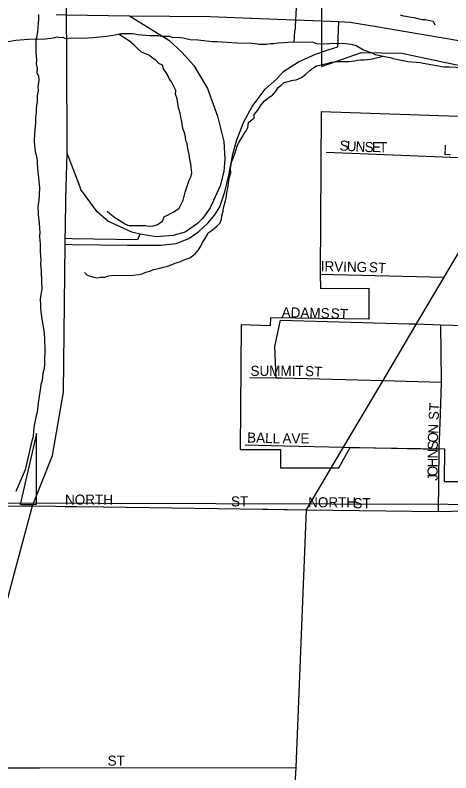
# Model space of a CAD drawing. Extents: x 1588073 to 2013523, y 1090242 to 1357120.
# Drawn here: x 1798757 to 1800917, y 1223743 to 1227498 of the extents above; entities that cross this region are included whole.
import ezdxf

# ---------------------------------------------------------------- set-up
doc = ezdxf.new("R2010")
doc.units = 0
for name, color, linetype in [('GM_X_City_Street', 7, 'Continuous'), ('GM_X_City_Street_Text', 7, 'Continuous'), ('GM_X_Corporation', 7, 'Continuous'), ('GM_X_County_Road', 7, 'Continuous'), ('GM_X_Interchange_Ramps', 7, 'Continuous'), ('GM_X_Minor_River', 7, 'Continuous'), ('GM_X_Section', 7, 'Continuous'), ('GM_X_State_Route', 7, 'Continuous'), ('GM_X_Township_Subdivision', 7, 'Continuous'), ('GM_X_Township_Subdivision_Text', 7, 'Continuous'), ('GM_X_US_Route', 7, 'Continuous')]:
    doc.layers.add(name, color=color, linetype=linetype)

msp = doc.modelspace()

# ---------------------------------------------------------------- linework, layer by layer
at = {"layer": 'GM_X_City_Street'}
for points in [[(1799006.2, 1226443.7), (1799007.7, 1226588.3), (1799015.6, 1226813.5)], [(1798843.2, 1225065.9), (1798942.8, 1225316.1), (1798997.5, 1225629.9), (1799005.3, 1226362.6), (1799005.6, 1226390.9), (1799006.2, 1226443.7)], [(1800201.9, 1225046.2), (1800332.9, 1225267.6)], [(1800856.5, 1225037.6), (1800858, 1225185.7)], [(1798501.3, 1223783.6), (1798574.1, 1224057.3), (1798658.5, 1224376.6), (1798754.2, 1224733.7), (1798843.2, 1225065.9)], [(1798632.2, 1225064.4), (1798790.4, 1225065.5)], [(1798843.2, 1225065.9), (1798958, 1225064.2), (1799005.8, 1225063.5), (1799060.6, 1225062.7)], [(1799060.6, 1225062.7), (1799197.2, 1225060.8), (1799984.5, 1225049.3)], [(1800031.1, 1221643.1), (1800031.1, 1221643.1), (1800047.7, 1221932.4), (1800071.5, 1222356), (1800150.7, 1223768.8), (1800201.9, 1225046.2)], [(1800093.2, 1225047.8), (1800106.2, 1225047.6), (1800201.9, 1225046.2)], [(1800201.9, 1225046.2), (1800856.5, 1225037.6), (1801303.3, 1225049.4), (1801324.7, 1225050)], [(1798506.3, 1223767.5), (1798506.3, 1223767.5), (1798877.6, 1223767.8), (1798877.6, 1223767.8)], [(1798877.6, 1223767.8), (1800150.7, 1223768.8)]]:
    msp.add_lwpolyline(points, dxfattribs=at)
at = {"layer": 'GM_X_Corporation'}
for points in [[(1800275.8, 1227597), (1800275.9, 1227243.8), (1800474.5, 1227312.3), (1800674.6, 1227308.8), (1801234.5, 1227190)], [(1801345.2, 1226981.8), (1800274.3, 1227018.9), (1800268.8, 1226214.5), (1800270.3, 1226144), (1800510.6, 1226144.1), (1800510.7, 1225991), (1800022.7, 1225998.4), (1800021.4, 1225958.4), (1799877.4, 1225963.4), (1799873.4, 1225344.6), (1800072.5, 1225344.7), (1800072.5, 1225254.6), (1800362.7, 1225254.7), (1800418.5, 1225356), (1800886.3, 1225348.3), (1800883.8, 1225186.9), (1801264, 1225187)]]:
    msp.add_lwpolyline(points, dxfattribs=at)
msp.add_lwpolyline([(1798781.4, 1225073.6), (1798862.5, 1225073.9), (1798862.4, 1225424.1)], close=True, dxfattribs=at)
at = {"layer": 'GM_X_County_Road'}
for points in [[(1800385.3, 1225356.1), (1800581.2, 1225687), (1800747.3, 1225967.3), (1800884.5, 1226198.9), (1800968.8, 1226341.2), (1801162.1, 1226667.6), (1801493, 1227179.7), (1801494.5, 1227182.6)], [(1800332.9, 1225267.6), (1800332.9, 1225267.6), (1800385.3, 1225356.1)], [(1798790.4, 1225065.5), (1798843.2, 1225065.9)], [(1799984.5, 1225049.3), (1800010.5, 1225049), (1800093.2, 1225047.8)]]:
    msp.add_lwpolyline(points, dxfattribs=at)
at = {"layer": 'GM_X_Interchange_Ramps'}
for points in [[(1799005.3, 1226362.6), (1799040.2, 1226361.8), (1799314, 1226357.2), (1799479.6, 1226357.2), (1799555.5, 1226366.4), (1799617.6, 1226391.7), (1799668.3, 1226426.3), (1799712, 1226467.7), (1799746.5, 1226509.1), (1799771.8, 1226548.2), (1799797.1, 1226621.9), (1799817.8, 1226711.6), (1799836.2, 1226808.2), (1799856.9, 1226879.6), (1799891.4, 1226969.3), (1799932.8, 1227045.2), (1799997.2, 1227130.4), (1800052.4, 1227181), (1800089.2, 1227220.2), (1800162.8, 1227266.2), (1800245.6, 1227305.3), (1800314.7, 1227328.3), (1800356.8, 1227341), (1800361.9, 1227466)], [(1799375.1, 1226412.6), (1799364.6, 1226385.2), (1799040.4, 1226390.1), (1799005.6, 1226390.9)]]:
    msp.add_lwpolyline(points, dxfattribs=at)
at = {"layer": 'GM_X_Minor_River'}
for points in [[(1800150.3, 1227539.1), (1800151.2, 1227529.3), (1800148.7, 1227507.3), (1800147.9, 1227467.3), (1800145.5, 1227447.3), (1800145.2, 1227431.3), (1800142.9, 1227417.3), (1800138.9, 1227363.9)], [(1798873.3, 1227500.6), (1798872.9, 1227478.6), (1798870, 1227438.6), (1798867.5, 1227414.6), (1798863, 1227388.7), (1798860.6, 1227370.7), (1798860.2, 1227348.7), (1798859.4, 1227314.6), (1798861, 1227292.6), (1798862.6, 1227274.5), (1798862.2, 1227256.5), (1798865.8, 1227234.4), (1798865.4, 1227214.4), (1798873, 1227196.2), (1798874.6, 1227176.1), (1798869.8, 1227140.2), (1798871.5, 1227124.1), (1798867, 1227100.2), (1798866.4, 1227070.1), (1798863.9, 1227048.2), (1798861.6, 1227034.2), (1798861.2, 1227016.2), (1798858.7, 1226988.2), (1798858.2, 1226964.1), (1798855.5, 1226930.1), (1798853, 1226910.2), (1798852.3, 1226874.1), (1798853.8, 1226852.1), (1798855.5, 1226838), (1798857.2, 1226821.9), (1798860.8, 1226803.8), (1798866.3, 1226779.7), (1798866, 1226763.7), (1798867.6, 1226743.6), (1798869.1, 1226719.6), (1798872.5, 1226693.4), (1798874.2, 1226675.4), (1798877.4, 1226641.3), (1798876.7, 1226607.2), (1798874.2, 1226579.2), (1798871.8, 1226561.3), (1798869.5, 1226545.3), (1798871, 1226525.2), (1798870.7, 1226509.2), (1798872.4, 1226493.2), (1798875.9, 1226469.1), (1798877.2, 1226439), (1798878.9, 1226422.9), (1798878.4, 1226400.9), (1798880, 1226380.8), (1798881.7, 1226364.8), (1798881, 1226330.7), (1798882.4, 1226302.7), (1798884.1, 1226286.6), (1798883.6, 1226264.6), (1798886.9, 1226228.5), (1798886.5, 1226210.4), (1798888.2, 1226196.4), (1798887.9, 1226180.4), (1798889, 1226140.3), (1798884.5, 1226114.3), (1798881.9, 1226088.4), (1798883.4, 1226062.3), (1798883, 1226042.3), (1798886.4, 1226016.2), (1798891.7, 1225982), (1798898.8, 1225935.8), (1798902, 1225897.7), (1798903.5, 1225873.6), (1798905.1, 1225857.6), (1798903.3, 1225767.4), (1798900.9, 1225747.5), (1798894.3, 1225721.6), (1798891.6, 1225687.6), (1798885.2, 1225667.7), (1798880.6, 1225639.7), (1798878.3, 1225621.7), (1798875.9, 1225605.8), (1798871.3, 1225575.8), (1798866.4, 1225529.8), (1798862, 1225513.9), (1798851, 1225464), (1798848.5, 1225438.1), (1798845.8, 1225408.1), (1798839.4, 1225388.1), (1798806.5, 1225244.6), (1798760.3, 1225137.3)], [(1800666.3, 1227499), (1800680.2, 1227494.7), (1800694.2, 1227492.5), (1800720, 1227487.9), (1800736, 1227485.6), (1800753.9, 1227481.3), (1800775.8, 1227476.8), (1800791.8, 1227476.5), (1800811.7, 1227472.1), (1800829.6, 1227467.7), (1800837.2, 1227449.6)], [(1798722.6, 1227367.4), (1798760.7, 1227374.7), (1798822.8, 1227379.5), (1798906.8, 1227379.8), (1798946.9, 1227385), (1798965, 1227390.7), (1798978.9, 1227386.4), (1798992.9, 1227388.1), (1799006.8, 1227381.8), (1799038.8, 1227385.2), (1799088.8, 1227384.2), (1799144.8, 1227387.1), (1799210.9, 1227393.8), (1799253, 1227401), (1799281.1, 1227406.4), (1799339.1, 1227407.3), (1799367, 1227402.7), (1799422.9, 1227397.6), (1799446.8, 1227397.1), (1799466.8, 1227396.7), (1799484.8, 1227394.3), (1799520.7, 1227393.6), (1799538.6, 1227387.3), (1799558.6, 1227388.9), (1799574.6, 1227386.6), (1799590.5, 1227386.2), (1799624.3, 1227377.6), (1799662.3, 1227374.8), (1799736.1, 1227367.3), (1799758, 1227366.9), (1799855.9, 1227360.9), (1799929.8, 1227359.5), (1799947.7, 1227357.1), (1799963.7, 1227354.8), (1800003.6, 1227354), (1800021.7, 1227357.6), (1800035.7, 1227357.3), (1800061.8, 1227360.8), (1800089.8, 1227362.3), (1800133.8, 1227365.4)], [(1799212.9, 1226526.4), (1799226.6, 1226514.1), (1799252.2, 1226495.6), (1799268, 1226485.3), (1799285.7, 1226472.9), (1799307.5, 1226460.5), (1799321.3, 1226456.2), (1799401.3, 1226454.6), (1799417.2, 1226452.3), (1799441.2, 1226453.8), (1799459.3, 1226459.4), (1799487.7, 1226476.9), (1799496.1, 1226498.8), (1799544.6, 1226523.8), (1799571, 1226541.3), (1799589.8, 1226581), (1799600.6, 1226620.9), (1799619.9, 1226680.6), (1799630.3, 1226700.4), (1799632.6, 1226716.4), (1799629.1, 1226742.5), (1799627.5, 1226760.6), (1799624, 1226782.7), (1799620.5, 1226806.8), (1799614.9, 1226828.9), (1799611.3, 1226845), (1799609.6, 1226861.1), (1799603.9, 1226875.2), (1799602.3, 1226895.3), (1799594.8, 1226919.4), (1799589.2, 1226935.6), (1799583.9, 1226969.7), (1799578.3, 1226991.9), (1799574.8, 1227012), (1799567.3, 1227038.2), (1799560.2, 1227082.4), (1799552.7, 1227106.6), (1799553.1, 1227124.6), (1799543.5, 1227144.8), (1799532, 1227167.1), (1799522.3, 1227181.3), (1799512.7, 1227201.5), (1799505, 1227215.7), (1799493.4, 1227231.9), (1799487.8, 1227250.1), (1799469.9, 1227258.4), (1799456.3, 1227272.7), (1799436.6, 1227287.1), (1799422.8, 1227297.4), (1799408.9, 1227303.7), (1799383.2, 1227314.2), (1799367.5, 1227328.6), (1799345.9, 1227351), (1799324.3, 1227369.5), (1799272.5, 1227402.2)], [(1800133.8, 1227365.4), (1800233.7, 1227363.4), (1800251.6, 1227357.1), (1800283.5, 1227356.4), (1800315.6, 1227357.8), (1800383.5, 1227358.4), (1800407.5, 1227356), (1800423.4, 1227353.6), (1800447.3, 1227347.1), (1800484.8, 1227326.4), (1800528.4, 1227309.5), (1800542.3, 1227303.2), (1800598, 1227292.1), (1800615.9, 1227287.7), (1800631.8, 1227283.4), (1800671.6, 1227274.6), (1800703.5, 1227267.9), (1800745.4, 1227265.1), (1800765.3, 1227262.7), (1800779.3, 1227260.4), (1800799.2, 1227256), (1800882.8, 1227242.3), (1800908.8, 1227241.8), (1801040.6, 1227235.2)], [(1799100.6, 1226222.2), (1799114.3, 1226209.9), (1799130.2, 1226203.6), (1799148.1, 1226199.2), (1799166, 1226196.9), (1799180.1, 1226198.6), (1799202.1, 1226200.2), (1799222.2, 1226205.8), (1799244.3, 1226209.3), (1799266.2, 1226206.9), (1799288.2, 1226208.5), (1799308.2, 1226208.1), (1799342.2, 1226209.4), (1799370.3, 1226212.8), (1799386.3, 1226216.5), (1799404.5, 1226224.2), (1799424.6, 1226229.8), (1799442.7, 1226237.4), (1799474.9, 1226244.8), (1799492.9, 1226248.5), (1799507, 1226252.2), (1799523.1, 1226257.9), (1799551.3, 1226269.3), (1799573.4, 1226274.9), (1799587.6, 1226282.6), (1799603.7, 1226288.3), (1799623.9, 1226295.9), (1799650.3, 1226315.4), (1799666.6, 1226335.1), (1799677, 1226353), (1799685.4, 1226370.8), (1799695.7, 1226386.6), (1799708.1, 1226404.4), (1799714.4, 1226418.3), (1799734.6, 1226431.9), (1799759.1, 1226453.5), (1799773.4, 1226469.2), (1799779.8, 1226487.1), (1799782, 1226501.1), (1799788.6, 1226527), (1799790.9, 1226543), (1799799.6, 1226576.9), (1799803.9, 1226590.8), (1799808.6, 1226626.8), (1799810.9, 1226640.7), (1799817.9, 1226688.7), (1799826.5, 1226718.5), (1799825, 1226738.6), (1799829.6, 1226768.6), (1799840.1, 1226794.4), (1799848.6, 1226816.2), (1799857.2, 1226848.1), (1799865.6, 1226866), (1799882.1, 1226893.7), (1799892.5, 1226911.5), (1799902.8, 1226925.3), (1799911.1, 1226941.2), (1799913.6, 1226965.2), (1799942.1, 1226988.6), (1799942.4, 1227004.7), (1799960.9, 1227026.3), (1799977.4, 1227054), (1799993.8, 1227073.8), (1800016.2, 1227091.3), (1800032.4, 1227101), (1800050.8, 1227122.7), (1800061.1, 1227138.5), (1800075.4, 1227150.2), (1800091.6, 1227163.9), (1800135.9, 1227175.1), (1800149.9, 1227176.8), (1800176.1, 1227188.3), (1800198.5, 1227205.9), (1800216.8, 1227221.5), (1800233, 1227235.2), (1800251.3, 1227246.9), (1800267.4, 1227250.6), (1800287.4, 1227254.2), (1800309.5, 1227259.8), (1800323.6, 1227265.5), (1800341.7, 1227267.1), (1800361.7, 1227268.7), (1800411.6, 1227267.7), (1800439.7, 1227271.2), (1800453.8, 1227274.9), (1800469.8, 1227276.6), (1800487.8, 1227276.2), (1800501.8, 1227278), (1800519.8, 1227279.6), (1800582.8, 1227294.9)]]:
    msp.add_lwpolyline(points, dxfattribs=at)
at = {"layer": 'GM_X_Section'}
msp.add_lwpolyline([(1796314.5, 1228634.1), (1797921.1, 1228670.8), (1801580.1, 1228628), (1801478.2, 1225070.5), (1796297.6, 1225086.2)], close=True, dxfattribs=at)
at = {"layer": 'GM_X_State_Route'}
for points in [[(1799013.3, 1227304.4), (1799012.4, 1227499.7), (1799023.8, 1228588.9), (1799024.2, 1228626.5), (1799028.6, 1229064.5)], [(1799324.1, 1227495.2), (1799518.9, 1227373.6), (1799584.1, 1227314.4), (1799643, 1227247.8), (1799711.6, 1227134.4), (1799760.7, 1226997.4), (1799792.5, 1226871.6), (1799796, 1226785), (1799792.5, 1226723.2), (1799773.1, 1226652.5), (1799723.6, 1226543), (1799688.3, 1226491.7), (1799661.8, 1226465.2), (1799600, 1226422.8), (1799538.2, 1226405.2), (1799458.7, 1226399.8), (1799375.1, 1226412.6), (1799335.7, 1226422.2), (1799216.7, 1226477.6), (1799164.4, 1226522.9), (1799083.6, 1226634.2), (1799079.2, 1226645.8)], [(1799079.2, 1226645.8), (1799053.2, 1226715.5), (1799015.6, 1226813.5), (1799013.3, 1227304.4)]]:
    msp.add_lwpolyline(points, dxfattribs=at)
at = {"layer": 'GM_X_Township_Subdivision'}
for points in [[(1801162.1, 1226667.6), (1800957.6, 1226791.2), (1800506.8, 1226808.4), (1800298.5, 1226817.8)], [(1800268.8, 1226214.5), (1800884.5, 1226198.9)], [(1800052.1, 1225700.8), (1800044.4, 1225855.1), (1800072.7, 1225987)], [(1800072.7, 1225987), (1800710.8, 1225968.4), (1800710.8, 1225968.4)], [(1800710.8, 1225968.4), (1800747.3, 1225967.3), (1800868.3, 1225963.8), (1801357.1, 1225949.5), (1801447.2, 1225946.9)], [(1800871.5, 1225685.8), (1800868.3, 1225963.8)], [(1799920.8, 1225702.5), (1800052.1, 1225700.8), (1800078.5, 1225700.1), (1800079.3, 1225700.1)], [(1800079.3, 1225700.1), (1800581.2, 1225687), (1800871.6, 1225679.3)], [(1800865.8, 1225519.2), (1800871.6, 1225679.3), (1800871.5, 1225685.8)], [(1800859.8, 1225352.5), (1800865.8, 1225519.2)], [(1799898.4, 1225368), (1800093.2, 1225363.2), (1800093.2, 1225363.2)], [(1800093.2, 1225363.2), (1800385.3, 1225356.1)], [(1800385.3, 1225356.1), (1800859.6, 1225346.8)], [(1800858, 1225185.7), (1800859.6, 1225346.8), (1800859.8, 1225352.5)]]:
    msp.add_lwpolyline(points, dxfattribs=at)
at = {"layer": 'GM_X_US_Route'}
for points in [[(1798960.8, 1227500.5), (1799012.4, 1227499.7), (1799324.1, 1227495.2)], [(1799324.1, 1227495.2), (1799724.5, 1227491.5), (1799925, 1227483.5)], [(1799925, 1227483.5), (1799928.4, 1227483.3), (1800143.4, 1227474.7)], [(1800143.4, 1227474.7), (1800148.9, 1227474.5), (1800361.9, 1227466), (1800418.9, 1227463.7), (1800567.8, 1227438.8)], [(1800567.8, 1227438.8), (1800587.2, 1227435.6), (1801542, 1227273.1), (1802152.3, 1227149.8)]]:
    msp.add_lwpolyline(points, dxfattribs=at)

# ---------------------------------------------------------------- texts
at = {"layer": 'GM_X_City_Street_Text'}
for s, p in [('NORTH', (1799004.4, 1225072)), ('ST', (1799827.2, 1225063.2)), ('NORTH', (1800210, 1225058.8)), ('ST', (1800434.4, 1225054.4)), ('ST', (1799215.6, 1223778.4))]:
    msp.add_text(s, height=50, rotation=0, dxfattribs=at).set_placement(p)
at = {"layer": 'GM_X_Township_Subdivision_Text'}
for s, rotation, p in [('S', 356.4458, (1800364.6, 1226827.6)), ('U', 356.4573, (1800399.8, 1226825.4)), ('N', 356.4573, (1800443.7, 1226822.7)), ('S', 358.323, (1800489.4, 1226819.9)), ('E', 359.9073, (1800526, 1226818.9)), ('T', 359.9956, (1800561.3, 1226818.8)), ('L', 356.8565, (1800879.4, 1226805.6)), ('IRVING', 358.8315, (1800271.8, 1226229.2)), ('ST', 356.4262, (1800509.8, 1226224.8)), ('ADAMS', 358.8549, (1800078.2, 1226000.4)), ('ST', 356.4262, (1800320.6, 1225996)), ('SUMMIT', 0, (1799924, 1225710)), ('ST', 356.4254, (1800193, 1225710)), ('ST', 86.4254, (1800856.2, 1225490)), ('N', 87.7919, (1800854.5, 1225422.8)), ('BALL', 358.4067, (1799906.7, 1225380)), ('AVE', 0, (1800082.4, 1225375.6)), ('O', 87.8575, (1800852.8, 1225378.9)), ('S', 88.5792, (1800852, 1225343.9)), ('N', 89.8251, (1800851.9, 1225300.2)), ('H', 89.9781, (1800851.8, 1225256.2)), ('O', 89.9781, (1800851.8, 1225212.2)), ('J', 90, (1800851.8, 1225190.2))]:
    msp.add_text(s, height=50, rotation=rotation, dxfattribs=at).set_placement(p)

doc.saveas('drawing.dxf')
